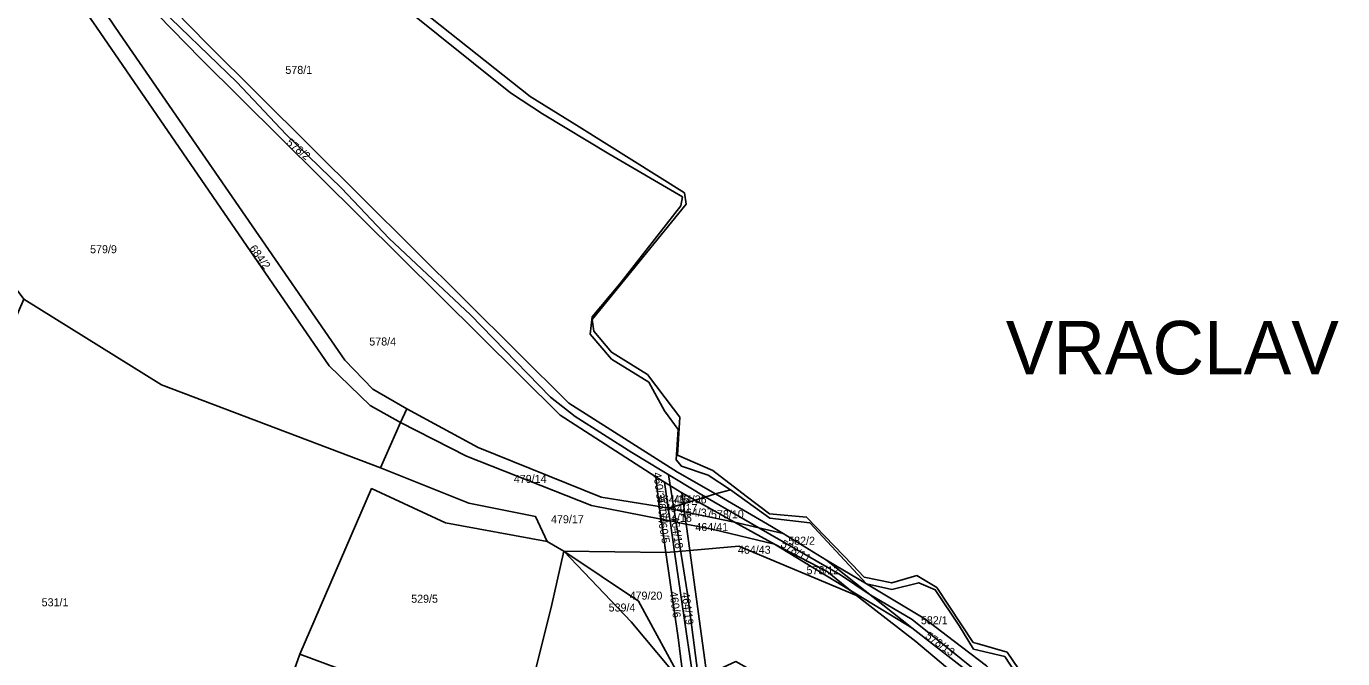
# Model space of a CAD drawing. Extents: x -629983 to -626385, y -1072828 to -1067897.
# Drawn here: x -627583.2 to -627089.7, y -1069550.4 to -1069313.4 of the extents above; entities that cross this region are included whole.
import ezdxf

# ---------------------------------------------------------------- set-up
doc = ezdxf.new("R2010")
doc.units = 0
for name, color, linetype in [('Default', 7, 'Continuous'), ('HOZ', 7, 'Continuous'), ('Parcela nároku', 7, 'Continuous'), ('Parcelní číslo', 7, 'Continuous'), ('Plocha PÚ', 7, 'Continuous'), ('Převzatý obvod_Vraclav', 7, 'Continuous'), ('voda', 7, 'Continuous')]:
    doc.layers.add(name, color=color, linetype=linetype)

msp = doc.modelspace()

# ---------------------------------------------------------------- linework, layer by layer
at = {"layer": 'HOZ'}
msp.add_lwpolyline([(-627421.78, -1069996.04), (-627408.61, -1069962.8), (-627394.45, -1069923.07), (-627386.36, -1069900.38), (-627356.75, -1069822.47), (-627337.43, -1069771.65), (-627325.35, -1069735.07), (-627324.61, -1069730.09), (-627323.57, -1069723.12), (-627323.95, -1069689.95), (-627326.13, -1069623.87), (-627327.32, -1069587.7), (-627335.38, -1069526.09), (-627342.44, -1069481.41)], dxfattribs=at)
at = {"layer": 'Parcela nároku'}
for points in [[(-627583.15, -1069264.51), (-627598.81, -1069242.61), (-627622.78, -1069217.95), (-627587.87, -1069269.14), (-627556.92, -1069313.71), (-627469.62, -1069440.57), (-627454.33, -1069455.51), (-627442.87, -1069461.88), (-627440.52, -1069456.67), (-627453.31, -1069449.31), (-627463.77, -1069438.44), (-627548.25, -1069316.09)], [(-627324.81, -1069488.6), (-627339.13, -1069480.44), (-627379.75, -1069454.55), (-627515.4, -1069319.93), (-627618.57, -1069214.56), (-627598.81, -1069242.61), (-627517.7, -1069325.48), (-627383, -1069459.06), (-627347.15, -1069482.18), (-627343.99, -1069484.22), (-627337.43, -1069488.19), (-627332.48, -1069490.93)], [(-627517.7, -1069325.48), (-627598.81, -1069242.61), (-627583.15, -1069264.51), (-627548.25, -1069316.09), (-627463.77, -1069438.44), (-627453.31, -1069449.31), (-627440.52, -1069456.67), (-627413.75, -1069471.16), (-627367.69, -1069489.87), (-627345.93, -1069493.32), (-627347.15, -1069482.18), (-627383, -1069459.06)], [(-627556.92, -1069313.71), (-627587.87, -1069269.14), (-627630.67, -1069367.65), (-627602.8, -1069390.7), (-627584.07, -1069415.57), (-627532.45, -1069447.67), (-627450.43, -1069478.79), (-627442.87, -1069461.88), (-627454.33, -1069455.51), (-627469.62, -1069440.57)], [(-627387.95, -1069506.5), (-627392.29, -1069497.12), (-627417.27, -1069492.05), (-627450.43, -1069478.79), (-627532.45, -1069447.67), (-627584.07, -1069415.57), (-627619.46, -1069497.12), (-627666.16, -1069469.88), (-627716.51, -1069585.55), (-627605.55, -1069622.32), (-627574.69, -1069633.25), (-627551.87, -1069641.76), (-627517.96, -1069653.42), (-627480.65, -1069548.74), (-627453.72, -1069486.59), (-627426.1, -1069499.39)], [(-627440.52, -1069456.67), (-627413.75, -1069471.16), (-627367.69, -1069489.87), (-627345.93, -1069493.32), (-627345.24, -1069498.07), (-627371.36, -1069493.01), (-627418.14, -1069474.42), (-627442.87, -1069461.88)], [(-627345.24, -1069498.07), (-627343.44, -1069510.58), (-627381.65, -1069510.05), (-627387.95, -1069506.5), (-627392.29, -1069497.12), (-627417.27, -1069492.05), (-627450.43, -1069478.79), (-627442.87, -1069461.88), (-627418.14, -1069474.42), (-627371.36, -1069493.01)], [(-627342.57, -1069494.01), (-627343.99, -1069484.22), (-627347.15, -1069482.18), (-627345.93, -1069493.32)], [(-627337.43, -1069488.19), (-627336.87, -1069492.27), (-627342.57, -1069494.01), (-627343.99, -1069484.22)], [(-627453.72, -1069486.59), (-627426.1, -1069499.39), (-627387.95, -1069506.5), (-627381.65, -1069510.05), (-627386.43, -1069531.17), (-627398.67, -1069579.98), (-627431.87, -1069566.76), (-627480.65, -1069548.74)], [(-627337.43, -1069488.19), (-627332.48, -1069490.93), (-627336.87, -1069492.27)], [(-627299.51, -1069503.46), (-627303.82, -1069500.81), (-627324.81, -1069488.6), (-627332.48, -1069490.93), (-627317.65, -1069499.16)], [(-627289.52, -1069499.44), (-627304.49, -1069497.73), (-627319.18, -1069487.04), (-627324.81, -1069488.6), (-627303.82, -1069500.81), (-627299.51, -1069503.46), (-627283.19, -1069513.49), (-627268.22, -1069522.27)], [(-627341.88, -1069498.74), (-627342.57, -1069494.01), (-627345.93, -1069493.32), (-627345.24, -1069498.07)], [(-627342.57, -1069494.01), (-627336.87, -1069492.27), (-627336.46, -1069495.27)], [(-627342.57, -1069494.01), (-627336.46, -1069495.27), (-627335.82, -1069499.95), (-627341.88, -1069498.74)], [(-627336.87, -1069492.27), (-627332.48, -1069490.93), (-627317.65, -1069499.16), (-627336.46, -1069495.27)], [(-627345.24, -1069498.07), (-627341.88, -1069498.74), (-627340.2, -1069510.3), (-627343.44, -1069510.58)], [(-627341.88, -1069498.74), (-627335.82, -1069499.95), (-627334.48, -1069509.8), (-627340.2, -1069510.3)], [(-627336.46, -1069495.27), (-627317.65, -1069499.16), (-627302.76, -1069507.41), (-627325.58, -1069501.99), (-627335.82, -1069499.95)], [(-627283.19, -1069513.49), (-627251.28, -1069538.83), (-627274.18, -1069524.76), (-627282.92, -1069517.74), (-627302.76, -1069507.41), (-627317.65, -1069499.16), (-627299.51, -1069503.46)], [(-627302.76, -1069507.41), (-627277.42, -1069522.77), (-627274.18, -1069524.76), (-627271.98, -1069526.74), (-627316.09, -1069508.2), (-627334.48, -1069509.8), (-627335.82, -1069499.95), (-627325.58, -1069501.99)], [(-627194.37, -1069602.74), (-627177.63, -1069626.85), (-627148.72, -1069664.45), (-627116.5, -1069688.84), (-627123.94, -1069698.07), (-627129.03, -1069692.38), (-627155.86, -1069668.53), (-627201.56, -1069631.19), (-627222.35, -1069613.82), (-627245.87, -1069595.67), (-627265.56, -1069581.74), (-627277.42, -1069573.8), (-627317.22, -1069551.48), (-627328.12, -1069556.45), (-627334.48, -1069509.8), (-627316.09, -1069508.2), (-627271.98, -1069526.74), (-627249.67, -1069543.94), (-627231.46, -1069559.34), (-627217.34, -1069574.26), (-627207.91, -1069584.5)], [(-627302.76, -1069507.41), (-627282.92, -1069517.74), (-627274.18, -1069524.76), (-627277.42, -1069522.77)], [(-627336.51, -1069560.27), (-627335.68, -1069565.62), (-627332.91, -1069619.68), (-627331.83, -1069644.72), (-627350.88, -1069636.09), (-627389.9, -1069618.55), (-627402.98, -1069612.67), (-627398.67, -1069579.98), (-627386.43, -1069531.17), (-627381.65, -1069510.05), (-627356.48, -1069536.58)], [(-627343.44, -1069510.58), (-627338.84, -1069542.54), (-627336.51, -1069560.27), (-627353.66, -1069528.87), (-627381.65, -1069510.05)], [(-627381.65, -1069510.05), (-627353.66, -1069528.87), (-627336.51, -1069560.27), (-627356.48, -1069536.58)], [(-627333.13, -1069558.73), (-627335.85, -1069540.22), (-627340.2, -1069510.3), (-627343.44, -1069510.58), (-627338.84, -1069542.54), (-627336.51, -1069560.27)], [(-627334.48, -1069509.8), (-627328.12, -1069556.45), (-627333.13, -1069558.73), (-627335.85, -1069540.22), (-627340.2, -1069510.3)], [(-627235.71, -1069543.56), (-627223.24, -1069553.11), (-627205.83, -1069568.59), (-627201.84, -1069579.11), (-627220.68, -1069562.55), (-627226.86, -1069557.76), (-627251.28, -1069538.83), (-627283.19, -1069513.49), (-627268.22, -1069522.27), (-627246.36, -1069535.48)], [(-627258.69, -1069524.41), (-627268.22, -1069522.27), (-627246.36, -1069535.48), (-627235.71, -1069543.56), (-627223.24, -1069553.11), (-627205.83, -1069568.59), (-627207.95, -1069562.39), (-627216.37, -1069549.5), (-627228.1, -1069546.76), (-627233.41, -1069538.2), (-627242.45, -1069524.53), (-627248.62, -1069521.91)], [(-627204.46, -1069582.29), (-627183.77, -1069611.23), (-627174.51, -1069624.83), (-627144.63, -1069663.86), (-627102.68, -1069694.97), (-627095.92, -1069699.69), (-627089.72, -1069702.42), (-627091.65, -1069705.26), (-627099.6, -1069701.62), (-627116.5, -1069688.84), (-627148.72, -1069664.45), (-627177.63, -1069626.85), (-627194.37, -1069602.74), (-627207.91, -1069584.5), (-627217.34, -1069574.26), (-627231.46, -1069559.34), (-627249.67, -1069543.94), (-627271.98, -1069526.74), (-627274.18, -1069524.76), (-627251.28, -1069538.83), (-627226.86, -1069557.76)], [(-627480.65, -1069548.74), (-627517.96, -1069653.42), (-627469.84, -1069669.97), (-627431.87, -1069566.76)]]:
    msp.add_lwpolyline(points, close=True, dxfattribs=at)
for points in [[(-627618.57, -1069214.56), (-627515.4, -1069319.93), (-627379.75, -1069454.55), (-627339.13, -1069480.44), (-627324.81, -1069488.6), (-627319.18, -1069487.04), (-627327.58, -1069481.55), (-627337.6, -1069478.19), (-627339.56, -1069475.87), (-627338.82, -1069464.41), (-627343.96, -1069457.43), (-627349.83, -1069446.71), (-627363.82, -1069438.09), (-627371.78, -1069428.71), (-627371.09, -1069422.3), (-627360.63, -1069409.9), (-627337.8, -1069380.59), (-627337.19, -1069377.29), (-627364.82, -1069361.18), (-627389.65, -1069346.2), (-627401.66, -1069338.27), (-627442.61, -1069305.38)], [(-627207.95, -1069562.39), (-627216.37, -1069549.5), (-627228.1, -1069546.76), (-627233.41, -1069538.2), (-627242.45, -1069524.53), (-627248.62, -1069521.91), (-627258.69, -1069524.41), (-627268.22, -1069522.27), (-627289.52, -1069499.44), (-627304.49, -1069497.73), (-627319.18, -1069487.04), (-627327.58, -1069481.55), (-627337.6, -1069478.19), (-627339.56, -1069475.87), (-627338.82, -1069464.41), (-627343.96, -1069457.43), (-627349.83, -1069446.71), (-627363.82, -1069438.09), (-627371.78, -1069428.71), (-627371.09, -1069422.3), (-627360.63, -1069409.9), (-627337.8, -1069380.59), (-627337.19, -1069377.29), (-627364.82, -1069361.18), (-627389.65, -1069346.2), (-627401.66, -1069338.27), (-627442.61, -1069305.38)], [(-627441.31, -1069302.27), (-627394.24, -1069339.61), (-627375.94, -1069351.06), (-627336.43, -1069375.78), (-627335.77, -1069380.04), (-627371.12, -1069423.29), (-627370.48, -1069427.6), (-627363.84, -1069435.54), (-627350.37, -1069443.9), (-627340.55, -1069456.75), (-627338.2, -1069459.83), (-627339.13, -1069474.11), (-627325.81, -1069479.83), (-627313.28, -1069489.46), (-627304.62, -1069496.12), (-627290.71, -1069497.3), (-627273.52, -1069515.21), (-627269.06, -1069519.86), (-627258.77, -1069521.96), (-627249.41, -1069519.22), (-627241.84, -1069523.74), (-627228.2, -1069544.27), (-627226.78, -1069544.67), (-627215.5, -1069547.88), (-627209.13, -1069557.24)]]:
    msp.add_lwpolyline(points, dxfattribs=at)
at = {"layer": 'Plocha PÚ'}
msp.add_lwpolyline([(-627209.13, -1069557.24), (-627215.5, -1069547.88), (-627226.78, -1069544.67), (-627228.2, -1069544.27), (-627241.84, -1069523.74), (-627249.41, -1069519.22), (-627258.77, -1069521.96), (-627269.06, -1069519.86), (-627273.52, -1069515.21), (-627290.71, -1069497.3), (-627304.62, -1069496.12), (-627313.28, -1069489.46), (-627325.81, -1069479.83), (-627339.13, -1069474.11), (-627338.2, -1069459.83), (-627340.55, -1069456.75), (-627350.37, -1069443.9), (-627363.84, -1069435.54), (-627370.48, -1069427.6), (-627371.12, -1069423.29), (-627335.77, -1069380.04), (-627336.43, -1069375.78), (-627375.94, -1069351.06), (-627394.24, -1069339.61), (-627441.31, -1069302.27)], dxfattribs=at)
at = {"layer": 'Převzatý obvod_Vraclav'}
msp.add_lwpolyline([(-627441.31, -1069302.27), (-627394.24, -1069339.61), (-627375.94, -1069351.06), (-627336.43, -1069375.78), (-627335.77, -1069380.04), (-627371.12, -1069423.29), (-627370.48, -1069427.6), (-627363.84, -1069435.54), (-627350.37, -1069443.9), (-627340.55, -1069456.75), (-627338.2, -1069459.83), (-627339.13, -1069474.11), (-627325.81, -1069479.83), (-627313.28, -1069489.46), (-627304.62, -1069496.12), (-627290.71, -1069497.3), (-627273.52, -1069515.21), (-627269.06, -1069519.86), (-627258.77, -1069521.96), (-627249.41, -1069519.22), (-627241.84, -1069523.74), (-627228.2, -1069544.27), (-627226.78, -1069544.67), (-627215.5, -1069547.88), (-627209.13, -1069557.24)], dxfattribs=at)
at = {"layer": 'voda'}
msp.add_lwpolyline([(-627608.69, -1069228.58), (-627567.33, -1069271.37), (-627536.18, -1069303.59), (-627504.31, -1069334.27), (-627485.76, -1069353.94), (-627464.97, -1069374.06), (-627447.22, -1069392.83), (-627416.71, -1069421.47), (-627386.71, -1069452.38), (-627377.38, -1069459.57), (-627356.25, -1069473.06), (-627328.64, -1069489.76), (-627308.58, -1069501.31), (-627278, -1069518.91), (-627267.24, -1069526.16), (-627251.07, -1069535.67), (-627238.49, -1069545.79), (-627221.22, -1069559.68), (-627209.33, -1069569.24), (-627201.32, -1069574.3)], dxfattribs=at)

# ---------------------------------------------------------------- texts
at = {"layer": 'Default'}
msp.add_text('VRACLAV', height=20, dxfattribs=at).set_placement((-627216, -1069443.78))
msp.add_text('VRACLAV', height=20, dxfattribs=at).set_placement((-627216, -1069443.78))
at = {"layer": 'Parcelní číslo'}
for s, p in [('578/1', (-627486.07, -1069331.18)), ('579/9', (-627559.27, -1069398.4)), ('578/4', (-627454.6, -1069432.99)), ('479/14', (-627400.44, -1069484.49)), ('464/36', (-627340.43, -1069492.16)), ('464/17', (-627343.88, -1069495.42)), ('464/37', (-627338.17, -1069497.11)), ('578/10', (-627326.52, -1069497.73)), ('479/17', (-627386.48, -1069499.6)), ('464/41', (-627332.37, -1069502.53)), ('464/43', (-627316.43, -1069511.05)), ('582/2', (-627297.57, -1069507.66)), ('578/12', (-627290.72, -1069518.7)), ('531/1', (-627577.43, -1069530.73)), ('529/5', (-627438.91, -1069529.41)), ('479/20', (-627357.03, -1069528.23)), ('539/4', (-627364.88, -1069532.69)), ('582/1', (-627247.83, -1069537.47))]:
    msp.add_text(s, height=3, dxfattribs=at).set_placement(p)
for s, rotation, p in [('578/2', 320.6271, (-627485.99, -1069357.37)), ('684/2', 305.9633, (-627499.73, -1069396.62)), ('460/3', 277.7124, (-627348.18, -1069480.72)), ('464/15', 359.7194, (-627346.8, -1069492.08)), ('460/4', 275.8886, (-627346.73, -1069490.08)), ('460/5', 279.9693, (-627346.51, -1069497.5)), ('464/16', 358.8053, (-627345.99, -1069498.91)), ('464/18', 277.8661, (-627341.56, -1069497.14)), ('578/11', 329.3951, (-627300.7, -1069508.19)), ('460/6', 278.0402, (-627342.11, -1069525.32)), ('464/19', 277.5641, (-627337.56, -1069525.66)), ('578/13', 324.188, (-627246.45, -1069542.43))]:
    msp.add_text(s, height=3, rotation=rotation, dxfattribs=at).set_placement(p)

doc.saveas('drawing.dxf')
